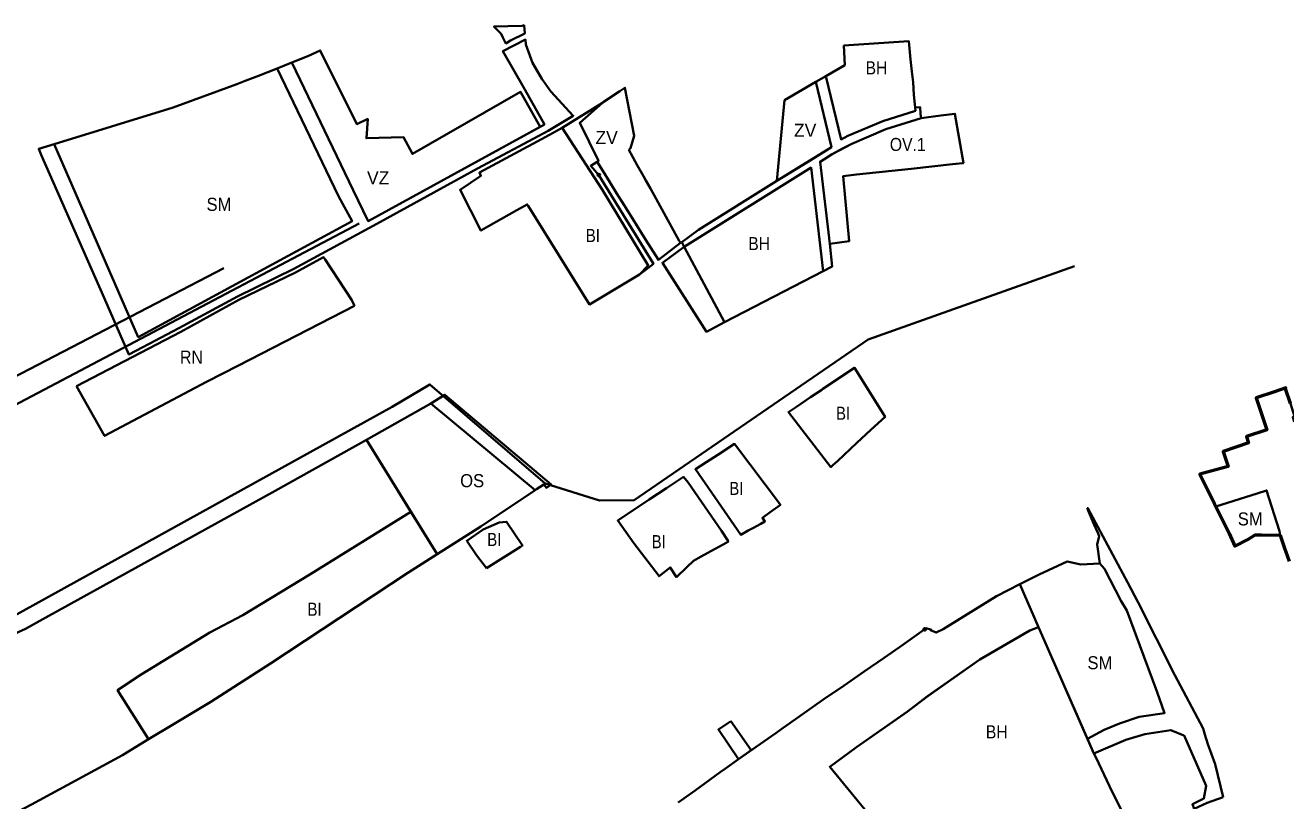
# Model space of a CAD drawing. Extents: x -650276 to -642489, y -1074311 to -1066720.
# Drawn here: x -648741 to -647583, y -1071099 to -1070387 of the extents above; entities that cross this region are included whole.
import ezdxf

# ---------------------------------------------------------------- set-up
doc = ezdxf.new("R2010")
doc.units = 0
doc.header["$LTSCALE"] = 4.8
doc.header["$PDMODE"] = 32
doc.header["$PDSIZE"] = 2.4
for name, color, linetype, lineweight in [('1', 7, 'Continuous', 35), ('11', 7, 'Continuous', 35), ('12', 7, 'Continuous', 35), ('15', 7, 'Continuous', 35), ('18', 7, 'Continuous', 35), ('2', 7, 'Continuous', 35), ('36', 7, 'Continuous', 35), ('40', 7, 'Continuous', 35), ('54', 7, 'Continuous', 35), ('60', 7, 'Continuous', 53), ('7', 7, 'Continuous', 35), ('9', 7, 'Continuous', 35)]:
    doc.layers.add(name, color=color, linetype=linetype, lineweight=lineweight)
doc.layers.add('62', color=7, linetype='Continuous')

msp = doc.modelspace()

# ---------------------------------------------------------------- linework, layer by layer
at = {"layer": '1'}
for points in [[(-647991.539, -1070492.016), (-647985.19, -1070488.804), (-647953.251, -1070475.276), (-647923.247, -1070465.749), (-647923.53, -1070462.75), (-647924.63, -1070451.09), (-647925.5, -1070439.63), (-647926.53, -1070429.76), (-647927.67, -1070418.74), (-647929.24, -1070401.97), (-647988.86, -1070405.95), (-647988.11, -1070423.93), (-648005.668, -1070434.145)], [(-648098.637, -1070659.682), (-648007.838, -1070612.851), (-648019, -1070518), (-648135.47, -1070590.61), (-648105.98, -1070645.91)], [(-648001.922, -1071067.83), (-647977.41, -1071049.74), (-647930.7, -1071017.18), (-647911.838, -1071002.919), (-647864.03, -1070969.3), (-647864.03, -1070969.3), (-647818.33, -1070942.91), (-647810.243, -1070939.825), (-647759.52, -1071055.67), (-647757.19, -1071059.66), (-647742.64, -1071090.72), (-647726.74, -1071122.48), (-647742.35, -1071129.43), (-647775.982, -1071148.001), (-647775.982, -1071148.001), (-647875.939, -1071221.104)]]:
    msp.add_lwpolyline(points, close=True, dxfattribs=at)
at = {"layer": '11'}
msp.add_lwpolyline([(-647927.14, -1070519), (-647889.27, -1070514.92), (-647886.09, -1070514.58), (-647879.89, -1070513.91), (-647879.16, -1070513.83), (-647887.08, -1070468.54), (-647899.87, -1070470.04), (-647917.98, -1070472.47), (-647950.48, -1070482.79), (-647981.81, -1070496.06), (-647990.295, -1070500.352), (-647999.756, -1070505.655), (-648010.831, -1070512.588), (-648002, -1070588), (-647984.03, -1070585.46), (-647989.5, -1070525.73), (-647977.41, -1070524.43)], close=True, dxfattribs=at)
at = {"layer": '12'}
for points in [[(-647569.92, -1070762.24), (-647573.88, -1070750.25), (-647575.58, -1070750.83), (-647576.81, -1070746.86), (-647575.09, -1070746.33), (-647578.79, -1070734.33), (-647583.38, -1070720.9), (-647583.22, -1070720.2), (-647593.6, -1070723.68), (-647610.33, -1070729.28), (-647600.53, -1070758.65), (-647619.2, -1070764.85), (-647617.36, -1070770.69)], [(-647617.36, -1070770.69), (-647619.12, -1070771.28), (-647640.66, -1070778.47), (-647636.12, -1070792.13)], [(-647636.12, -1070792.13), (-647654.89, -1070797.23), (-647662.26, -1070799.23), (-647650.908, -1070822.34), (-647647.405, -1070829.08), (-647609.58, -1070817.06), (-647600.8, -1070814.27), (-647588.89, -1070851.67), (-647588.4, -1070855.25), (-647584.6, -1070866.3), (-647580.22, -1070879.3)]]:
    msp.add_lwpolyline(points, dxfattribs=at)
at = {"layer": '15'}
msp.add_line((-648272.453, -1070814.072), (-648271.1, -1070813.17), dxfattribs=at)
for points in [[(-648303.705, -1070395.035), (-648302.028, -1070398.436), (-648299.32, -1070403.93), (-648295.18, -1070401.23), (-648281.907, -1070394.762), (-648282.582, -1070387.276), (-648284.37, -1070387.85), (-648310.275, -1070388.476)], [(-648550.72, -1070626.869), (-648636.757, -1070673.431), (-648655.178, -1070631.294), (-648714.161, -1070496.376), (-648728.255, -1070500.709), (-648725.835, -1070506.221), (-648668.207, -1070637.453), (-648645.331, -1070689.546), (-648632.652, -1070682.82), (-648599.66, -1070665.32), (-648545.76, -1070636.22), (-648494.04, -1070610.73), (-648417.855, -1070569.57), (-648325.21, -1070518.84), (-648264.56, -1070486.34), (-648260.57, -1070484.2), (-648237.475, -1070470.361), (-648257.96, -1070448.17), (-648266.416, -1070436.404), (-648274.808, -1070421.647), (-648280.974, -1070405.11), (-648281.388, -1070400.523), (-648302.01, -1070411.05), (-648282.01, -1070446.35), (-648263.859, -1070478.393), (-648425.835, -1070567.021), (-648439.409, -1070538.729), (-648495.666, -1070421.476), (-648509.227, -1070426.957), (-648452.97, -1070544.21), (-648440.531, -1070567.236)], [(-648007.838, -1070612.851), (-647999.588, -1070608.596), (-648002, -1070588), (-648010.831, -1070512.588), (-647999.756, -1070505.655), (-647981.81, -1070496.06), (-647950.48, -1070482.79), (-647917.98, -1070472.47), (-647918.54, -1070468.61), (-647918.95, -1070462.36), (-647923.53, -1070462.75), (-647923.247, -1070465.749), (-647953.251, -1070475.276), (-647985.19, -1070488.804), (-647991.539, -1070492.016), (-648005.668, -1070434.145), (-648014.63, -1070439.36), (-648000.442, -1070499.336), (-648019.789, -1070511.293), (-648050.38, -1070530.2), (-648122.57, -1070575), (-648137.78, -1070586.25), (-648135.47, -1070590.61), (-648019, -1070518)], [(-648135.47, -1070590.61), (-648155.582, -1070605.295), (-648115.057, -1070668.651), (-648098.637, -1070659.682)], [(-648092.72, -1071025.89), (-648104.12, -1071033.78), (-648085.73, -1071060.92), (-648074.12, -1071052.75)]]:
    msp.add_lwpolyline(points, close=True, dxfattribs=at)
for points in [[(-648213.87, -1070524.8), (-648221.359, -1070516.349), (-648215.48, -1070512.59), (-648214.34, -1070511.86), (-648231.53, -1070476.99), (-648210.48, -1070458.42), (-648247.67, -1070481.57), (-648211, -1070538), (-648168.575, -1070607.847), (-648176.54, -1070616.09)], [(-648176.54, -1070616.09), (-648169.28, -1070610.49), (-648163.8, -1070606.27), (-648213.87, -1070524.8), (-648221.359, -1070516.349), (-648215.48, -1070512.59), (-648214.34, -1070511.86), (-648231.53, -1070476.99), (-648210.48, -1070458.42), (-648247.67, -1070481.57), (-648211, -1070538)], [(-648176.54, -1070616.09), (-648169.28, -1070610.49), (-648163.8, -1070606.27), (-648213.87, -1070524.8)], [(-648211, -1070538), (-648168.575, -1070607.847), (-648176.54, -1070616.09)], [(-648271.1, -1070813.17), (-648267.8, -1070810.96), (-648264.38, -1070808.66), (-648262.15, -1070811.96), (-648257.61, -1070808.91), (-648355.275, -1070726.455), (-648360.83, -1070729.87), (-648366.739, -1070733.501), (-648368.163, -1070734.376), (-648272.453, -1070814.072)], [(-647659.01, -1071032.66), (-647685.1, -1070983.93), (-647719.06, -1070916.45), (-647728.35, -1070899.11), (-647764.84, -1070830.47), (-647765.72, -1070830.64)], [(-647765.72, -1070830.64), (-647759.08, -1070845.74), (-647755.87, -1070853.02), (-647754.6, -1070856.11), (-647756.45, -1070863.95), (-647753.81, -1070881.3)], [(-647753.81, -1070881.3), (-647749.75, -1070886.1), (-647734.48, -1070915.94), (-647729.27, -1070924.35), (-647701.45, -1070999.4)], [(-647701.45, -1070999.4), (-647694.54, -1071018.549), (-647718, -1071022), (-647736, -1071028), (-647750, -1071034), (-647765.408, -1071042.223), (-647759.52, -1071055.67), (-647730.17, -1071043.21), (-647712.74, -1071037.99), (-647688.9, -1071034.18), (-647676.96, -1071039.014)], [(-647676.96, -1071039.014), (-647676.9, -1071039.03), (-647676.45, -1071039.22), (-647656.443, -1071085.369), (-647658.55, -1071097.02), (-647669.02, -1071102.33), (-647667.35, -1071106.38), (-647655.47, -1071100.98), (-647640.727, -1071095.819)], [(-647640.727, -1071095.819), (-647648.106, -1071065.551), (-647654.747, -1071047.095), (-647657.699, -1071038.232), (-647659.01, -1071032.66)]]:
    msp.add_lwpolyline(points, dxfattribs=at)
msp.add_point((-648213.87, -1070524.8), dxfattribs=at)
at = {"layer": '18'}
for points in [[(-648636.757, -1070673.431), (-648550.72, -1070626.869), (-648440.531, -1070567.236), (-648452.97, -1070544.21), (-648509.227, -1070426.957), (-648526.28, -1070433.85), (-648538.611, -1070438.388), (-648546.377, -1070441.246), (-648604.92, -1070462.79), (-648714.161, -1070496.376), (-648655.178, -1070631.294)], [(-647736, -1071028), (-647718, -1071022), (-647694.54, -1071018.549), (-647701.45, -1070999.4), (-647729.27, -1070924.35), (-647734.48, -1070915.94), (-647749.75, -1070886.1), (-647753.81, -1070881.3), (-647771.47, -1070882.27), (-647783.95, -1070879.58), (-647809.74, -1070891.31), (-647827.527, -1070900.351), (-647810.243, -1070939.825), (-647765.408, -1071042.223), (-647750, -1071034)]]:
    msp.add_lwpolyline(points, close=True, dxfattribs=at)
for points in [[(-647588.4, -1070855.25), (-647588.89, -1070851.67), (-647600.8, -1070814.27), (-647609.58, -1070817.06), (-647647.405, -1070829.08)], [(-647647.405, -1070829.08), (-647635.11, -1070853.786), (-647629.92, -1070865.35), (-647618.01, -1070859.42), (-647611.3, -1070854.9), (-647605.64, -1070854.99), (-647588.4, -1070855.25)]]:
    msp.add_lwpolyline(points, dxfattribs=at)
at = {"layer": '2'}
for points in [[(-648247.67, -1070481.57), (-648262.69, -1070489.67), (-648323.59, -1070522.48), (-648322.18, -1070525.44), (-648341.41, -1070538.42), (-648322.16, -1070575.76), (-648289.22, -1070557.15), (-648279.736, -1070551.783), (-648278.89, -1070553.14), (-648222.58, -1070643.48), (-648176.54, -1070616.09), (-648168.575, -1070607.847), (-648211, -1070538)], [(-648032.601, -1070737.472), (-648039.82, -1070742.33), (-648000.85, -1070792.88), (-647999.06, -1070791.2), (-647994.63, -1070787.05), (-647994.63, -1070787.05), (-647982.89, -1070776.05), (-647976.97, -1070770.51), (-647964.21, -1070758.77), (-647951.11, -1070746.78), (-647979.17, -1070701.65), (-648008.28, -1070720.96), (-648009.29, -1070721.79), (-648019.49, -1070728.65)], [(-648114.77, -1070788.08), (-648125.2, -1070794.79), (-648083.65, -1070854.89), (-648076.73, -1070851.07), (-648074.41, -1070849.79), (-648072.59, -1070848.79), (-648065.35, -1070844.8), (-648061.52, -1070842.68), (-648063.76, -1070839.49), (-648056.61, -1070834.26), (-648047.17, -1070827.35), (-648089.27, -1070771.57), (-648104.78, -1070781.65)], [(-648167.6, -1070822.53), (-648196.65, -1070841.7), (-648181.75, -1070862.74), (-648158.58, -1070892.98), (-648148.34, -1070884.92), (-648142.79, -1070893.78), (-648133.14, -1070884.6), (-648127, -1070878.75), (-648122.72, -1070876.44), (-648111.24, -1070870.11), (-648099.85, -1070863.82), (-648094.9, -1070861.09), (-648095.42, -1070860.3), (-648101.45, -1070851.34), (-648132.03, -1070807.05), (-648136.08, -1070801.79), (-648151.77, -1070812.11)], [(-648540.7, -1070928.6), (-648571.14, -1070944.67), (-648634.07, -1070983.17), (-648655.76, -1070997.5), (-648627.39, -1071042.65), (-648605.3, -1071029.34), (-648570.23, -1071008.2), (-648515.46, -1070972.94), (-648389.33, -1070889.79), (-648362.519, -1070872.788), (-648386.587, -1070833.807), (-648479.18, -1070891.26)], [(-648317.14, -1070885.48), (-648285.72, -1070865.96), (-648284.02, -1070864.91), (-648298.78, -1070842.92), (-648305.33, -1070843.62), (-648320.02, -1070850.16), (-648335.19, -1070860.49), (-648326.41, -1070873.55)]]:
    msp.add_lwpolyline(points, close=True, dxfattribs=at)
msp.add_lwpolyline([(-647875.939, -1071221.104), (-648001.922, -1071067.83), (-647977.41, -1071049.74), (-647930.96, -1071017.383), (-647912.11, -1071003.11), (-647864.29, -1070969.503), (-647818.33, -1070942.91), (-647810.243, -1070939.825), (-647827.527, -1070900.351), (-647848.89, -1070911.21), (-647897.76, -1070941.62), (-647904.13, -1070944.78), (-647909.42, -1070942.63), (-647908.63, -1070942.1), (-647913.45, -1070940.79), (-647934.9, -1070955.87), (-647952.01, -1070967.82), (-647970.19, -1070980.45), (-647988.81, -1070993.27), (-648008.34, -1071006.32), (-648030.24, -1071021.91), (-648044.82, -1071032.25), (-648051.48, -1071036.97), (-648062.53, -1071044.59), (-648085.73, -1071060.92), (-648097.61, -1071069.37), (-648102.55, -1071072.86), (-648125.53, -1071089.51), (-648141.12, -1071100.71)], dxfattribs=at)
msp.add_point((-647914.73, -1070941.682), dxfattribs=at)
at = {"layer": '36'}
msp.add_lwpolyline([(-648495.666, -1070421.476), (-648439.409, -1070538.729), (-648425.835, -1070567.021), (-648267.801, -1070480.55), (-648285.75, -1070448.49), (-648385.085, -1070505.351), (-648393.14, -1070490.07), (-648427.41, -1070491.08), (-648426.05, -1070473.34), (-648436.22, -1070478.01), (-648469.77, -1070410.47), (-648481.18, -1070415.62)], close=True, dxfattribs=at)
at = {"layer": '40'}
msp.add_line((-648214.34, -1070511.86), (-648215.48, -1070512.59), dxfattribs=at)
for points in [[(-648186.441, -1070501.65), (-648186.088, -1070501.313), (-648184.791, -1070500.073), (-648181.386, -1070488.724), (-648189.93, -1070444.71), (-648194.56, -1070447.8), (-648194.56, -1070447.799), (-648209.82, -1070457.98), (-648210.48, -1070458.42), (-648231.53, -1070476.99), (-648214.34, -1070511.86)], [(-648166.63, -1070537.28), (-648170.72, -1070529.92), (-648172.96, -1070525.9), (-648178.7, -1070515.58), (-648184.54, -1070505.07), (-648186.441, -1070501.65)], [(-648215.48, -1070512.59), (-648210.19, -1070521.07), (-648203.83, -1070531.25), (-648197.59, -1070541.27), (-648190.71, -1070552.3), (-648182.98, -1070564.68), (-648171.02, -1070583.86), (-648159.23, -1070602.75), (-648138.93, -1070587.1)], [(-648138.93, -1070587.1), (-648140.05, -1070585.09), (-648166.63, -1070537.28)]]:
    msp.add_lwpolyline(points, dxfattribs=at)
msp.add_lwpolyline([(-648014.63, -1070439.36), (-648000.442, -1070499.336), (-648050.38, -1070530.2), (-648043.43, -1070456.12)], close=True, dxfattribs=at)
at = {"layer": '54'}
msp.add_line((-648876.429, -1070775.252), (-648558.121, -1070610.206), dxfattribs=at)
for points in [[(-648433.898, -1070569.36), (-648868.299, -1070798.03), (-648871.326, -1070799.464)], [(-648756.915, -1070932.76), (-648403.845, -1070737.419), (-648368.964, -1070716.905), (-648263.103, -1070807.79), (-648213.358, -1070823.563), (-648181.392, -1070823.076), (-647966.625, -1070675.686), (-647777.125, -1070608.309)]]:
    msp.add_lwpolyline(points, dxfattribs=at)
at = {"layer": '60'}
msp.add_lwpolyline([(-647578.79, -1070734.33), (-647583.38, -1070720.9), (-647583.22, -1070720.2), (-647593.6, -1070723.68), (-647610.33, -1070729.28), (-647600.53, -1070758.65), (-647619.2, -1070764.85), (-647617.36, -1070770.69), (-647640.66, -1070778.47), (-647636.12, -1070792.13), (-647662.26, -1070799.23), (-647635.11, -1070853.786), (-647629.92, -1070865.35), (-647618.01, -1070859.42), (-647611.3, -1070854.9), (-647605.64, -1070854.99), (-647588.4, -1070855.25), (-647584.6, -1070866.3), (-647580.22, -1070879.3)], dxfattribs=at)
at = {"layer": '7'}
for points in [[(-648438.13, -1070644.73), (-648440.8, -1070639.72), (-648465.28, -1070602.24), (-648466.61, -1070600.21), (-648492.47, -1070614.2), (-648544.42, -1070639.42), (-648597.74, -1070668.62), (-648693.45, -1070718.46)], [(-648693.45, -1070718.46), (-648667.72, -1070764.15), (-648574.27, -1070714.5), (-648544.906, -1070699.451), (-648438.13, -1070644.73)]]:
    msp.add_lwpolyline(points, dxfattribs=at)
msp.add_lwpolyline([(-648866.341, -1071000.881), (-648828.353, -1071043.265), (-648785.386, -1071084.634), (-648758.423, -1071107.756), (-648752.967, -1071111.861), (-648734.849, -1071102.599), (-648651.375, -1071057.109), (-648627.39, -1071042.65), (-648655.76, -1070997.5), (-648634.07, -1070983.17), (-648571.14, -1070944.67), (-648540.7, -1070928.6), (-648479.18, -1070891.26), (-648386.587, -1070833.807), (-648427.25, -1070767.95), (-648511.09, -1070814.7), (-648721.54, -1070930.88), (-648740.25, -1070941.21), (-648774.23, -1070956.42)], close=True, dxfattribs=at)
at = {"layer": '9'}
msp.add_lwpolyline([(-648368.163, -1070734.376), (-648427.25, -1070767.95), (-648362.519, -1070872.788), (-648322.17, -1070847.2), (-648272.45, -1070814.075)], close=True, dxfattribs=at)

# ---------------------------------------------------------------- texts
at = {"layer": '62'}
for s, width, p in [('BH', 0.9, (-647969.069, -1070432.39)), ('OV.1', 0.9, (-647946.769, -1070502.709)), ('SM', 0.95, (-648574.138, -1070557.646)), ('BI', 0.85, (-648225.838, -1070586.256)), ('BH', 0.9, (-648076.769, -1070593.709)), ('RN', 0.9, (-648598.428, -1070697.883)), ('BI', 0.85, (-647996.127, -1070749.398)), ('OS', 0.95, (-648341.265, -1070811.272)), ('BI', 0.85, (-648094.127, -1070818.398)), ('SM', 0.95, (-647627.328, -1070846.374)), ('BI', 0.85, (-648316.397, -1070865.265)), ('BI', 0.85, (-648165.397, -1070867.265)), ('BI', 0.85, (-648481.397, -1070929.265)), ('SM', 0.95, (-647765.328, -1070978.374)), ('BH', 0.9, (-647858.64, -1071041.819))]:
    msp.add_text(s, height=12, dxfattribs=dict(at, width=width)).set_placement(p)
for s, p in [('ZV', (-648217.069, -1070496.39)), ('ZV', (-648034.769, -1070489.709)), ('VZ', (-648426.778, -1070533.286))]:
    msp.add_text(s, height=12, dxfattribs=at).set_placement(p)

doc.saveas('drawing.dxf')
